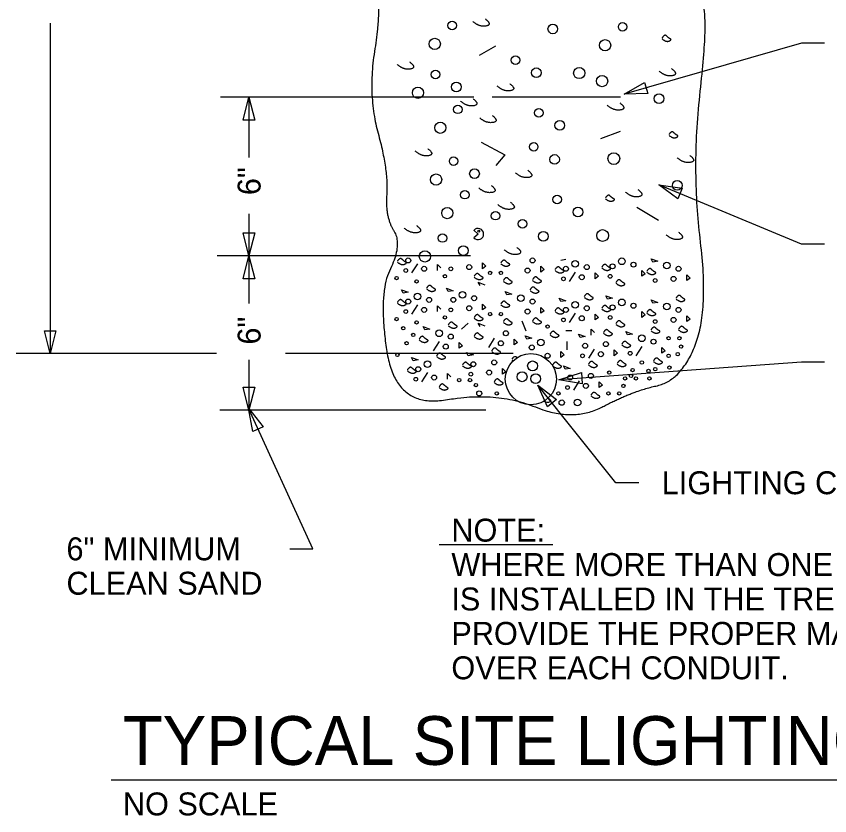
# Model space of a CAD drawing. Extents: x 10111 to 10157.2, y 10072.4 to 10116.1.
# Drawn here: x 10111.58 to 10135.23, y 10073.69 to 10096.92 of the extents above; entities that cross this region are included whole.
import ezdxf

# ---------------------------------------------------------------- set-up
doc = ezdxf.new("R2010")
doc.units = 0
for name, color, linetype in [('G-ANNO-TEXT', 7, 'Continuous'), ('G-DETL-LINE', 7, 'Continuous'), ('G-DETL-OTLN', 7, 'Continuous'), ('G-DETL-PATT', 7, 'Continuous')]:
    doc.layers.add(name, color=color, linetype=linetype)

msp = doc.modelspace()

# ---------------------------------------------------------------- linework, layer by layer
at = {"layer": 'G-ANNO-TEXT'}
for p, q in [((10112.564, 10096.716), (10112.564, 10087.114)), ((10134.41, 10096.136), (10129.25, 10094.653)), ((10135.076, 10096.136), (10134.41, 10096.136)), ((10124.882, 10094.567), (10117.519, 10094.567)), ((10118.345, 10094.567), (10118.345, 10092.814)), ((10134.41, 10090.297), (10130.261, 10092.021)), ((10118.345, 10091.178), (10118.345, 10089.954)), ((10135.076, 10090.297), (10134.41, 10090.297)), ((10124.79, 10089.954), (10117.426, 10089.954)), ((10118.345, 10089.954), (10118.345, 10088.574)), ((10117.398, 10087.114), (10111.582, 10087.114)), ((10126.026, 10087.114), (10119.412, 10087.114)), ((10118.345, 10086.934), (10118.345, 10085.475)), ((10134.41, 10086.866), (10127.357, 10086.355)), ((10135.076, 10086.866), (10134.41, 10086.866)), ((10129.011, 10083.362), (10126.742, 10086.197)), ((10125.227, 10085.475), (10117.501, 10085.475)), ((10120.201, 10081.442), (10118.333, 10085.528)), ((10129.678, 10083.362), (10129.011, 10083.362)), ((10119.534, 10081.442), (10120.201, 10081.442)), ((10123.87, 10081.566), (10127.181, 10081.566)), ((10114.344, 10074.731), (10154.756, 10074.731))]:
    msp.add_line(p, q, dxfattribs=at)
for points in [[(10129.937, 10094.677), (10129.25, 10094.653), (10129.845, 10094.997)], [(10118.178, 10093.9), (10118.345, 10094.567), (10118.512, 10093.9)], [(10130.813, 10091.611), (10130.261, 10092.021), (10130.941, 10091.919)], [(10118.512, 10090.621), (10118.345, 10089.954), (10118.178, 10090.621)], [(10118.178, 10089.287), (10118.345, 10089.954), (10118.512, 10089.287)], [(10112.731, 10087.781), (10112.564, 10087.114), (10112.398, 10087.781)], [(10128.034, 10086.237), (10127.357, 10086.355), (10128.01, 10086.569)], [(10118.512, 10086.141), (10118.345, 10085.475), (10118.178, 10086.141)], [(10127.028, 10085.572), (10126.742, 10086.197), (10127.288, 10085.78)], [(10118.458, 10084.852), (10118.333, 10085.528), (10118.761, 10084.991)]]:
    msp.add_lwpolyline(points, close=True, dxfattribs=at)
at = {"layer": 'G-DETL-LINE'}
msp.add_open_spline([(10121.996, 10101.13), (10121.895, 10098.19), (10122.199, 10097.176), (10121.794, 10094.642), (10122.401, 10092.412), (10122.3, 10091.095), (10122.806, 10090.284), (10122.098, 10088.865), (10122.604, 10085.52), (10125.541, 10086.027), (10127.768, 10085.115), (10129.49, 10086.027), (10130.908, 10086.331), (10131.718, 10088.358), (10131.212, 10092.514), (10131.718, 10096.973), (10131.313, 10097.683), (10131.92, 10098.19), (10131.617, 10100.825)], degree=2, dxfattribs=at)
at = {"layer": 'G-DETL-OTLN'}
msp.add_lwpolyline([(10125.413, 10094.58), (10129.15, 10094.58)], dxfattribs=at)
for centre, radius in [((10126.54, 10086.372), 0.742), ((10126.59, 10086.758), 0.143), ((10126.59, 10086.758), 0.143), ((10126.286, 10086.442), 0.143), ((10126.286, 10086.442), 0.143), ((10126.681, 10086.385), 0.143)]:
    msp.add_circle(centre, radius, dxfattribs=at)
at = {"layer": 'G-DETL-PATT'}
for p, q in [((10125.045, 10095.791), (10125.518, 10096.055)), ((10128.571, 10093.368), (10129.15, 10093.579)), ((10125.097, 10093.263), (10125.782, 10092.894)), ((10125.782, 10092.894), (10125.518, 10092.578)), ((10129.624, 10091.366), (10130.255, 10090.997)), ((10125.004, 10090.589), (10124.882, 10090.698)), ((10125.004, 10090.589), (10124.886, 10090.478)), ((10123.243, 10089.725), (10123.073, 10089.458)), ((10123.825, 10089.53), (10123.825, 10089.7)), ((10123.825, 10089.7), (10123.922, 10089.603)), ((10125.135, 10089.579), (10125.135, 10089.749)), ((10125.135, 10089.749), (10125.232, 10089.652)), ((10125.232, 10089.652), (10125.135, 10089.579)), ((10126.832, 10089.482), (10126.832, 10089.652)), ((10126.832, 10089.652), (10126.929, 10089.555)), ((10127.559, 10089.846), (10127.414, 10089.822)), ((10130.081, 10089.773), (10130.033, 10089.87)), ((10130.033, 10089.87), (10130.227, 10089.797)), ((10130.227, 10089.797), (10130.081, 10089.773)), ((10126.929, 10089.555), (10126.832, 10089.482)), ((10127.826, 10089.482), (10127.656, 10089.215)), ((10128.408, 10089.288), (10128.408, 10089.458)), ((10128.408, 10089.458), (10128.505, 10089.361)), ((10129.766, 10089.361), (10129.766, 10089.53)), ((10129.766, 10089.53), (10129.863, 10089.433)), ((10129.863, 10089.433), (10129.766, 10089.361)), ((10131.075, 10089.239), (10131.075, 10089.409)), ((10131.075, 10089.409), (10131.172, 10089.312)), ((10125.062, 10089.094), (10125.013, 10089.191)), ((10125.013, 10089.191), (10125.207, 10089.118)), ((10128.505, 10089.361), (10128.408, 10089.288)), ((10131.172, 10089.312), (10131.075, 10089.239)), ((10122.831, 10088.871), (10122.782, 10088.968)), ((10122.782, 10088.968), (10122.976, 10088.896)), ((10124.14, 10088.92), (10124.092, 10089.017)), ((10124.092, 10089.017), (10124.286, 10088.944)), ((10124.286, 10088.944), (10124.14, 10088.92)), ((10122.976, 10088.896), (10122.831, 10088.871)), ((10125.838, 10088.823), (10125.789, 10088.92)), ((10125.789, 10088.92), (10125.983, 10088.847)), ((10125.983, 10088.847), (10125.838, 10088.823)), ((10127.414, 10088.629), (10127.365, 10088.726)), ((10127.365, 10088.726), (10127.559, 10088.653)), ((10128.772, 10088.701), (10128.723, 10088.798)), ((10128.723, 10088.798), (10128.917, 10088.726)), ((10128.917, 10088.726), (10128.772, 10088.701)), ((10123.243, 10088.531), (10123.073, 10088.264)), ((10123.825, 10088.337), (10123.825, 10088.507)), ((10123.825, 10088.507), (10123.922, 10088.41)), ((10125.135, 10088.386), (10125.135, 10088.556)), ((10125.135, 10088.556), (10125.232, 10088.459)), ((10125.232, 10088.459), (10125.135, 10088.386)), ((10126.832, 10088.289), (10126.832, 10088.459)), ((10126.832, 10088.459), (10126.929, 10088.362)), ((10127.559, 10088.653), (10127.414, 10088.629)), ((10130.081, 10088.58), (10130.033, 10088.677)), ((10130.033, 10088.677), (10130.227, 10088.604)), ((10130.227, 10088.604), (10130.081, 10088.58)), ((10126.929, 10088.362), (10126.832, 10088.289)), ((10127.826, 10088.289), (10127.656, 10088.022)), ((10128.408, 10088.095), (10128.408, 10088.264)), ((10128.408, 10088.264), (10128.505, 10088.167)), ((10129.766, 10088.167), (10129.766, 10088.337)), ((10129.766, 10088.337), (10129.863, 10088.24)), ((10129.863, 10088.24), (10129.766, 10088.167)), ((10124.722, 10087.997), (10124.528, 10087.828)), ((10125.062, 10087.9), (10125.013, 10087.997)), ((10125.013, 10087.997), (10125.207, 10087.925)), ((10126.274, 10088.07), (10126.395, 10087.779)), ((10128.505, 10088.167), (10128.408, 10088.095)), ((10131.075, 10088.046), (10131.075, 10088.216)), ((10131.075, 10088.216), (10131.172, 10088.119)), ((10131.172, 10088.119), (10131.075, 10088.046)), ((10123.461, 10087.803), (10123.413, 10087.9)), ((10123.413, 10087.9), (10123.607, 10087.828)), ((10123.607, 10087.828), (10123.461, 10087.803)), ((10127.729, 10087.779), (10127.559, 10087.779)), ((10128.291, 10087.653), (10128.291, 10087.823)), ((10128.291, 10087.823), (10128.388, 10087.726)), ((10129.354, 10087.658), (10129.305, 10087.755)), ((10129.305, 10087.755), (10129.499, 10087.682)), ((10125.474, 10087.561), (10125.304, 10087.294)), ((10126.056, 10087.366), (10126.056, 10087.536)), ((10126.056, 10087.536), (10126.153, 10087.439)), ((10126.371, 10087.633), (10126.565, 10087.561)), ((10126.42, 10087.536), (10126.371, 10087.633)), ((10126.565, 10087.561), (10126.42, 10087.536)), ((10127.972, 10087.585), (10127.923, 10087.682)), ((10127.923, 10087.682), (10128.117, 10087.609)), ((10128.117, 10087.609), (10127.972, 10087.585)), ((10129.499, 10087.682), (10129.354, 10087.658)), ((10123.874, 10087.463), (10123.704, 10087.196)), ((10124.456, 10087.269), (10124.456, 10087.439)), ((10124.456, 10087.439), (10124.553, 10087.342)), ((10124.553, 10087.342), (10124.456, 10087.269)), ((10126.153, 10087.439), (10126.056, 10087.366)), ((10127.584, 10087.463), (10127.584, 10087.221)), ((10129.766, 10087.318), (10129.596, 10087.051)), ((10130.348, 10087.124), (10130.348, 10087.294)), ((10130.348, 10087.294), (10130.445, 10087.196)), ((10124.722, 10087.051), (10124.674, 10087.148)), ((10124.674, 10087.148), (10124.868, 10087.075)), ((10124.868, 10087.075), (10124.722, 10087.051)), ((10127.414, 10087.172), (10127.511, 10087.075)), ((10127.414, 10087.002), (10127.414, 10087.172)), ((10127.511, 10087.075), (10127.414, 10087.002)), ((10128.384, 10087.245), (10128.214, 10086.978)), ((10128.966, 10087.051), (10128.966, 10087.221)), ((10128.966, 10087.221), (10129.063, 10087.124)), ((10129.063, 10087.124), (10128.966, 10087.051)), ((10130.445, 10087.196), (10130.348, 10087.124)), ((10123.122, 10086.905), (10123.073, 10087.002)), ((10123.073, 10087.002), (10123.267, 10086.93)), ((10123.267, 10086.93), (10123.122, 10086.905)), ((10123.534, 10086.565), (10123.364, 10086.298)), ((10125.716, 10086.517), (10125.716, 10086.687)), ((10125.716, 10086.687), (10125.813, 10086.59)), ((10125.813, 10086.59), (10125.716, 10086.517)), ((10127.535, 10086.663), (10127.487, 10086.76)), ((10127.487, 10086.76), (10127.681, 10086.687)), ((10127.681, 10086.687), (10127.535, 10086.663)), ((10124.116, 10086.371), (10124.116, 10086.541)), ((10124.116, 10086.541), (10124.213, 10086.444)), ((10127.947, 10086.323), (10127.778, 10086.056)), ((10128.529, 10086.129), (10128.529, 10086.298)), ((10128.529, 10086.298), (10128.626, 10086.201)), ((10128.626, 10086.201), (10128.529, 10086.129))]:
    msp.add_line(p, q, dxfattribs=at)
for points in [[(10126.14, 10086.997), (10126.129, 10087.005), (10126.108, 10087.017), (10126.086, 10087.024), (10126.063, 10087.024), (10126.039, 10087.013), (10126.013, 10086.99), (10125.987, 10086.953)], [(10125.987, 10086.929), (10126.022, 10086.904)], [(10126.922, 10085.735), (10126.924, 10085.734), (10126.964, 10085.714), (10127, 10085.704), (10127.032, 10085.701), (10127.06, 10085.704), (10127.082, 10085.711), (10127.1, 10085.72), (10127.113, 10085.73), (10127.12, 10085.74), (10127.122, 10085.748), (10127.12, 10085.757), (10127.114, 10085.766), (10127.104, 10085.775), (10127.092, 10085.786), (10127.077, 10085.798), (10127.06, 10085.811), (10127.043, 10085.825)]]:
    msp.add_lwpolyline(points, dxfattribs=at)
for centre, radius in [((10124.255, 10096.65), 0.124), ((10127.178, 10096.551), 0.141), ((10129.208, 10096.609), 0.124), ((10123.746, 10096.116), 0.163), ((10128.699, 10096.075), 0.163), ((10126.095, 10095.64), 0.124), ((10123.768, 10095.228), 0.124), ((10126.702, 10095.276), 0.141), ((10127.946, 10095.268), 0.163), ((10128.61, 10095.035), 0.163), ((10123.258, 10094.694), 0.163), ((10124.374, 10094.863), 0.141), ((10130.266, 10094.524), 0.141), ((10124.417, 10094.212), 0.124), ((10126.774, 10094.111), 0.124), ((10123.908, 10093.678), 0.163), ((10127.381, 10093.747), 0.141), ((10126.623, 10093.121), 0.124), ((10128.951, 10092.781), 0.172), ((10124.295, 10092.708), 0.124), ((10127.229, 10092.757), 0.141), ((10124.902, 10092.344), 0.141), ((10123.786, 10092.174), 0.163), ((10130.794, 10092.004), 0.141), ((10124.62, 10091.733), 0.124), ((10127.302, 10091.592), 0.124), ((10124.111, 10091.199), 0.163), ((10127.908, 10091.228), 0.141), ((10125.514, 10091.123), 0.124), ((10126.298, 10090.886), 0.124), ((10123.971, 10090.473), 0.124), ((10125.025, 10090.673), 0.0257), ((10126.905, 10090.522), 0.141), ((10128.626, 10090.546), 0.172), ((10124.577, 10090.109), 0.141), ((10122.976, 10089.822), 0.0727), ((10123.461, 10089.939), 0.163), ((10126.589, 10089.822), 0.0727), ((10129.184, 10089.797), 0.097), ((10123.437, 10089.579), 0.0727), ((10124.747, 10089.628), 0.0727), ((10127.559, 10089.579), 0.0727), ((10127.826, 10089.725), 0.097), ((10128.166, 10089.628), 0.0727), ((10128.917, 10089.652), 0.0727), ((10129.523, 10089.7), 0.0727), ((10130.493, 10089.676), 0.097), ((10130.833, 10089.579), 0.0727), ((10122.904, 10089.53), 0.0542), ((10124.043, 10089.361), 0.0485), ((10124.213, 10089.579), 0.0542), ((10125.353, 10089.458), 0.0485), ((10125.668, 10089.458), 0.0485), ((10126.444, 10089.53), 0.0727), ((10128.02, 10089.336), 0.0727), ((10128.845, 10089.361), 0.0542), ((10122.637, 10089.312), 0.0485), ((10123.219, 10089.215), 0.0485), ((10127.487, 10089.288), 0.0542), ((10130.154, 10089.239), 0.0542), ((10130.687, 10089.288), 0.0727), ((10122.976, 10088.629), 0.0727), ((10123.243, 10088.774), 0.097), ((10123.583, 10088.677), 0.0727), ((10124.286, 10088.677), 0.0727), ((10124.553, 10088.823), 0.097), ((10124.892, 10088.726), 0.0727), ((10126.25, 10088.726), 0.097), ((10126.589, 10088.629), 0.0727), ((10129.184, 10088.604), 0.097), ((10123.437, 10088.386), 0.0727), ((10124.747, 10088.434), 0.0727), ((10127.559, 10088.386), 0.0727), ((10127.826, 10088.531), 0.097), ((10128.166, 10088.434), 0.0727), ((10128.917, 10088.459), 0.0727), ((10129.523, 10088.507), 0.0727), ((10130.493, 10088.483), 0.097), ((10130.833, 10088.386), 0.0727), ((10122.904, 10088.337), 0.0542), ((10124.213, 10088.386), 0.0542), ((10125.353, 10088.264), 0.0485), ((10125.668, 10088.264), 0.0485), ((10126.444, 10088.337), 0.0727), ((10128.845, 10088.167), 0.0542), ((10122.637, 10088.119), 0.0485), ((10123.219, 10088.022), 0.0485), ((10124.043, 10088.167), 0.0485), ((10127.487, 10088.095), 0.0542), ((10128.02, 10088.143), 0.0727), ((10130.154, 10088.046), 0.0542), ((10130.687, 10088.095), 0.0727), ((10122.831, 10087.852), 0.0485), ((10123.874, 10087.706), 0.097), ((10125.813, 10087.706), 0.0727), ((10127.026, 10087.9), 0.0485), ((10123.122, 10087.658), 0.0485), ((10124.213, 10087.609), 0.0727), ((10126.832, 10087.439), 0.097), ((10129.766, 10087.561), 0.097), ((10130.105, 10087.463), 0.0727), ((10130.542, 10087.561), 0.0485), ((10130.857, 10087.561), 0.0485), ((10122.928, 10087.415), 0.0485), ((10124.068, 10087.318), 0.0727), ((10125.668, 10087.415), 0.0727), ((10126.565, 10087.294), 0.0727), ((10128.117, 10087.342), 0.0727), ((10128.723, 10087.391), 0.0727), ((10130.906, 10087.318), 0.0485), ((10122.661, 10087.075), 0.0485), ((10127.026, 10087.051), 0.0727), ((10128.044, 10087.051), 0.0542), ((10128.578, 10087.099), 0.0727), ((10129.426, 10087.124), 0.0542), ((10130.542, 10087.051), 0.0485), ((10130.809, 10087.099), 0.0485), ((10123.534, 10086.808), 0.097), ((10124.868, 10086.808), 0.0727), ((10125.474, 10086.857), 0.0727), ((10129.766, 10086.857), 0.0485), ((10123.267, 10086.663), 0.0727), ((10124.795, 10086.517), 0.0542), ((10125.328, 10086.565), 0.0727), ((10128.82, 10086.565), 0.0485), ((10129.499, 10086.638), 0.0485), ((10129.96, 10086.614), 0.0485), ((10130.154, 10086.663), 0.0485), ((10130.566, 10086.711), 0.0485), ((10123.195, 10086.371), 0.0542), ((10123.728, 10086.42), 0.0727), ((10124.456, 10086.347), 0.0485), ((10124.771, 10086.347), 0.0485), ((10127.681, 10086.42), 0.0727), ((10128.287, 10086.468), 0.0727), ((10129.281, 10086.396), 0.0485), ((10129.451, 10086.468), 0.0485), ((10129.596, 10086.396), 0.0485), ((10129.984, 10086.396), 0.0485), ((10124.941, 10086.201), 0.0485), ((10127.608, 10086.129), 0.0542), ((10128.141, 10086.177), 0.0727), ((10129.232, 10086.177), 0.0485), ((10125.038, 10085.959), 0.0727), ((10125.547, 10085.959), 0.0485), ((10127.341, 10085.959), 0.0485), ((10128.796, 10085.959), 0.0485), ((10129.111, 10085.959), 0.0485), ((10127.438, 10085.692), 0.0767), ((10127.899, 10085.692), 0.097)]:
    msp.add_circle(centre, radius, dxfattribs=at)
msp.add_arc((10125.004, 10090.589), 0.163, 223.1288, 138.4277, dxfattribs=at)
for points in [[(10125.213, 10096.842), (10125.432, 10096.672), (10125.044, 10096.599), (10124.85, 10096.769)], [(10130.354, 10096.26), (10130.475, 10096.162), (10130.645, 10096.235), (10130.548, 10096.284), (10130.427, 10096.405), (10130.354, 10096.284)], [(10123.016, 10095.592), (10123.234, 10095.422), (10122.846, 10095.349), (10122.652, 10095.519)], [(10130.63, 10095.397), (10130.848, 10095.228), (10130.46, 10095.155), (10130.266, 10095.325)], [(10125.926, 10094.961), (10126.144, 10094.791), (10125.756, 10094.718), (10125.562, 10094.888)], [(10124.859, 10094.524), (10125.077, 10094.354), (10124.689, 10094.281), (10124.495, 10094.451)], [(10129.126, 10094.402), (10129.345, 10094.232), (10128.957, 10094.16), (10128.763, 10094.33)], [(10125.416, 10094.038), (10125.635, 10093.868), (10125.247, 10093.796), (10125.053, 10093.965)], [(10130.557, 10093.456), (10130.678, 10093.359), (10130.848, 10093.431), (10130.751, 10093.48), (10130.63, 10093.601), (10130.557, 10093.48)], [(10123.544, 10093.072), (10123.762, 10092.902), (10123.374, 10092.83), (10123.18, 10092.999)], [(10131.158, 10092.878), (10131.376, 10092.708), (10130.988, 10092.635), (10130.794, 10092.805)], [(10126.454, 10092.441), (10126.672, 10092.271), (10126.284, 10092.198), (10126.09, 10092.368)], [(10125.387, 10092.004), (10125.605, 10091.834), (10125.217, 10091.762), (10125.023, 10091.931)], [(10129.654, 10091.883), (10129.873, 10091.713), (10129.485, 10091.64), (10129.291, 10091.81)], [(10128.71, 10091.612), (10128.831, 10091.515), (10129.001, 10091.587), (10128.904, 10091.636), (10128.783, 10091.757), (10128.71, 10091.636)], [(10125.944, 10091.519), (10126.163, 10091.349), (10125.775, 10091.276), (10125.581, 10091.446)], [(10123.219, 10090.837), (10123.437, 10090.667), (10123.049, 10090.595), (10122.855, 10090.764)], [(10130.833, 10090.643), (10131.051, 10090.473), (10130.663, 10090.4), (10130.469, 10090.57)], [(10126.129, 10090.206), (10126.347, 10090.036), (10125.959, 10089.964), (10125.765, 10090.133)], [(10122.661, 10089.773), (10122.782, 10089.676), (10122.952, 10089.749), (10122.855, 10089.797), (10122.734, 10089.919), (10122.661, 10089.797)], [(10125.668, 10089.725), (10125.789, 10089.628), (10125.959, 10089.7), (10125.862, 10089.749), (10125.741, 10089.87), (10125.668, 10089.749)], [(10128.602, 10089.603), (10128.723, 10089.506), (10128.893, 10089.579), (10128.796, 10089.628), (10128.675, 10089.749), (10128.602, 10089.628)], [(10124.892, 10089.336), (10125.013, 10089.239), (10125.183, 10089.312), (10125.086, 10089.361), (10124.965, 10089.482), (10124.892, 10089.361)], [(10127.244, 10089.53), (10127.365, 10089.433), (10127.535, 10089.506), (10127.438, 10089.555), (10127.317, 10089.676), (10127.244, 10089.555)], [(10129.911, 10089.482), (10130.033, 10089.385), (10130.202, 10089.458), (10130.105, 10089.506), (10129.984, 10089.628), (10129.911, 10089.506)], [(10125.741, 10089.215), (10125.862, 10089.118), (10126.032, 10089.191), (10125.935, 10089.239), (10125.813, 10089.361), (10125.741, 10089.239)], [(10126.589, 10089.239), (10126.711, 10089.142), (10126.88, 10089.215), (10126.783, 10089.263), (10126.662, 10089.385), (10126.589, 10089.263)], [(10129.013, 10089.158), (10129.135, 10089.061), (10129.304, 10089.134), (10129.207, 10089.182), (10129.086, 10089.304), (10129.013, 10089.182)], [(10123.51, 10088.993), (10123.631, 10088.896), (10123.801, 10088.968), (10123.704, 10089.017), (10123.583, 10089.138), (10123.51, 10089.017)], [(10126.517, 10088.944), (10126.638, 10088.847), (10126.808, 10088.92), (10126.711, 10088.968), (10126.589, 10089.09), (10126.517, 10088.968)], [(10128.093, 10088.75), (10128.214, 10088.653), (10128.384, 10088.726), (10128.287, 10088.774), (10128.166, 10088.896), (10128.093, 10088.774)], [(10130.76, 10088.701), (10130.881, 10088.604), (10131.051, 10088.677), (10130.954, 10088.726), (10130.833, 10088.847), (10130.76, 10088.726)], [(10122.661, 10088.58), (10122.782, 10088.483), (10122.952, 10088.556), (10122.855, 10088.604), (10122.734, 10088.726), (10122.661, 10088.604)], [(10125.668, 10088.531), (10125.789, 10088.434), (10125.959, 10088.507), (10125.862, 10088.556), (10125.741, 10088.677), (10125.668, 10088.556)], [(10128.602, 10088.41), (10128.723, 10088.313), (10128.893, 10088.386), (10128.796, 10088.434), (10128.675, 10088.556), (10128.602, 10088.434)], [(10124.892, 10088.143), (10125.013, 10088.046), (10125.183, 10088.119), (10125.086, 10088.167), (10124.965, 10088.289), (10124.892, 10088.167)], [(10127.244, 10088.337), (10127.365, 10088.24), (10127.535, 10088.313), (10127.438, 10088.362), (10127.317, 10088.483), (10127.244, 10088.362)], [(10129.911, 10088.289), (10130.033, 10088.192), (10130.202, 10088.264), (10130.105, 10088.313), (10129.984, 10088.434), (10129.911, 10088.313)], [(10124.14, 10087.925), (10124.262, 10087.828), (10124.431, 10087.9), (10124.334, 10087.949), (10124.213, 10088.07), (10124.14, 10087.949)], [(10125.741, 10088.022), (10125.862, 10087.925), (10126.032, 10087.997), (10125.935, 10088.046), (10125.813, 10088.167), (10125.741, 10088.046)], [(10126.589, 10088.046), (10126.711, 10087.949), (10126.88, 10088.022), (10126.783, 10088.07), (10126.662, 10088.192), (10126.589, 10088.07)], [(10129.013, 10087.965), (10129.135, 10087.868), (10129.304, 10087.941), (10129.207, 10087.989), (10129.086, 10088.111), (10129.013, 10087.989)], [(10127.099, 10087.658), (10127.22, 10087.561), (10127.39, 10087.633), (10127.293, 10087.682), (10127.171, 10087.803), (10127.099, 10087.682)], [(10128.651, 10087.706), (10128.772, 10087.609), (10128.942, 10087.682), (10128.845, 10087.73), (10128.723, 10087.852), (10128.651, 10087.73)], [(10130.033, 10087.779), (10130.154, 10087.682), (10130.324, 10087.755), (10130.227, 10087.803), (10130.105, 10087.925), (10130.033, 10087.803)], [(10130.833, 10087.803), (10130.954, 10087.706), (10131.124, 10087.779), (10131.027, 10087.828), (10130.906, 10087.949), (10130.833, 10087.828)], [(10123.292, 10087.512), (10123.413, 10087.415), (10123.583, 10087.488), (10123.486, 10087.536), (10123.364, 10087.658), (10123.292, 10087.536)], [(10124.892, 10087.609), (10125.013, 10087.512), (10125.183, 10087.585), (10125.086, 10087.633), (10124.965, 10087.755), (10124.892, 10087.633)], [(10125.401, 10087.172), (10125.523, 10087.075), (10125.692, 10087.148), (10125.595, 10087.196), (10125.474, 10087.318), (10125.401, 10087.196)], [(10129.184, 10087.366), (10129.305, 10087.269), (10129.475, 10087.342), (10129.378, 10087.391), (10129.257, 10087.512), (10129.184, 10087.391)], [(10123.801, 10087.027), (10123.922, 10086.93), (10124.092, 10087.002), (10123.995, 10087.051), (10123.874, 10087.172), (10123.801, 10087.051)], [(10124.553, 10086.76), (10124.674, 10086.663), (10124.844, 10086.735), (10124.747, 10086.784), (10124.625, 10086.905), (10124.553, 10086.784)], [(10127.171, 10086.76), (10127.293, 10086.663), (10127.462, 10086.735), (10127.365, 10086.784), (10127.244, 10086.905), (10127.171, 10086.784)], [(10128.214, 10086.784), (10128.335, 10086.687), (10128.505, 10086.76), (10128.408, 10086.808), (10128.287, 10086.93), (10128.214, 10086.808)], [(10129.051, 10086.808), (10129.172, 10086.711), (10129.342, 10086.784), (10129.245, 10086.832), (10129.124, 10086.954), (10129.051, 10086.832)], [(10130.105, 10086.881), (10130.227, 10086.784), (10130.396, 10086.857), (10130.299, 10086.905), (10130.178, 10087.027), (10130.105, 10086.905)], [(10122.952, 10086.614), (10123.073, 10086.517), (10123.243, 10086.59), (10123.146, 10086.638), (10123.025, 10086.76), (10122.952, 10086.638)], [(10125.474, 10086.274), (10125.595, 10086.177), (10125.765, 10086.25), (10125.668, 10086.298), (10125.547, 10086.42), (10125.474, 10086.298)], [(10123.874, 10086.129), (10123.995, 10086.031), (10124.165, 10086.104), (10124.068, 10086.153), (10123.946, 10086.274), (10123.874, 10086.153)], [(10128.287, 10085.886), (10128.408, 10085.789), (10128.578, 10085.862), (10128.481, 10085.91), (10128.36, 10086.031), (10128.287, 10085.91)]]:
    msp.add_open_spline(points, degree=2, dxfattribs=at)

# ---------------------------------------------------------------- texts
at = {"layer": 'G-ANNO-TEXT'}
for p in [(10118.684, 10091.72), (10118.684, 10087.377)]:
    msp.add_text('6"', height=0.6667, rotation=90, dxfattribs=at).set_placement(p)
for s, height, p in [('LIGHTING CIRCUIT CONDUCTORS', 0.66667, (10130.344, 10083.029)), ('NOTE:', 0.6667, (10124.229, 10081.652)), ('6" MINIMUM', 0.6667, (10113.041, 10081.109)), ('WHERE MORE THAN ONE CONDUIT', 0.66667, (10124.229, 10080.652)), ('CLEAN SAND', 0.6667, (10113.041, 10080.109)), ('IS INSTALLED IN THE TRENCH,', 0.66667, (10124.229, 10079.652)), ('PROVIDE THE PROPER MARKER TAPE', 0.66667, (10124.229, 10078.652)), ('OVER EACH CONDUIT.', 0.66667, (10124.229, 10077.652)), ('TYPICAL SITE LIGHTING TRENCH DETAIL', 1.41667, (10114.681, 10075.164)), ('NO SCALE', 0.6667, (10114.681, 10073.696))]:
    msp.add_text(s, height=height, dxfattribs=at).set_placement(p)

doc.saveas('drawing.dxf')
